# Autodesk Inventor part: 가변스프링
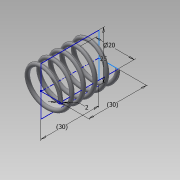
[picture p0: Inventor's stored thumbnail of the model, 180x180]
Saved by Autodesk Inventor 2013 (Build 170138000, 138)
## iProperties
Created: 2019-01
Part Number: 가변스프링
Material: 일반
Document SubType Name: Modeling
Designer: Administrator
Density: 1 g/cm^3
Author: Administrator
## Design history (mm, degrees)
sketch "스케치1"
  geometry: L1 (0, 0)-(10, 0); L2 (10, 0)-(10, 30); L3 (10, 30)-(0, 30); L4 (0, 30)-(0, 0); C1 r 1 at (10, 0)
  constraints: 8 end point, 2 parallel, 1 centre point, 1 coincident, 1 horizontal, 1 perpendicular
  dimensions: "d0" = 2 diameter of C1; "d2" = 20 diameter of L2 L4; "d3" = 30 distance between parallel lines of L1 L3 (derived)
feature "코일1" sketch "스케치1" pitch "d4" = 10; turns "d6" = 5; dims "d5" = 30 (= d3), "d7" = 0, angle "d8" = 90 deg, angle "d9" = 90 deg, "d10" = 0, "d11" = 0
sketch "스케치2"
  geometry: L1 (30, 12.5)-(0, 12.5); L2 (0, 12.5)-(0, -12.5); L3 (0, -12.5)-(30, -12.5); L4 (30, -12.5)-(30, 12.5); 2 further points
  constraints: 8 end point, 2 parallel, 1 coincident, 1 horizontal, 1 midpoint, 1 perpendicular
  dimensions: "d12" = 25 distance between parallel lines of L3 L1; "d14" = 30 distance between parallel lines of L2 L4 (derived)
extrude "돌출1" sketch "스케치2" stored distance "d15" = 25; taper "d16" = 0 deg
node "솔리드1"
